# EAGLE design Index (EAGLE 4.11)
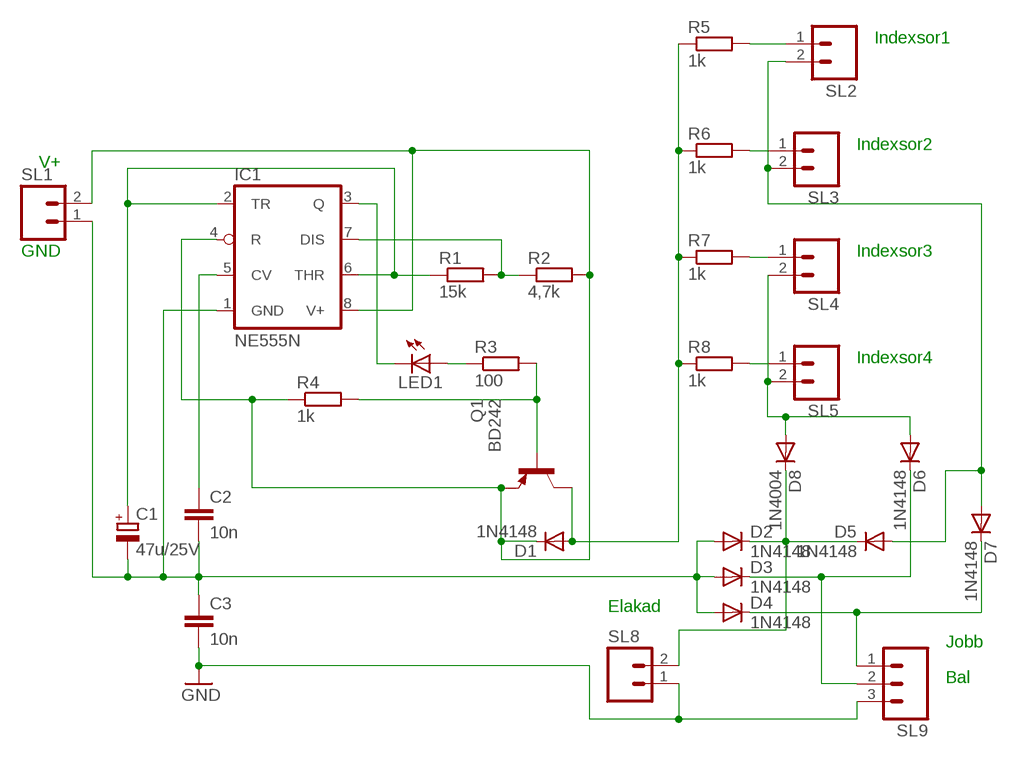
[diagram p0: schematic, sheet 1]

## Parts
C1  47u/25V  CPOL-EUE5-6  [E5-6]
C2  10n  C-EU050-025X075  [C050-025X075]
C3  10n  C-EU050-025X075  [C050-025X075]
D1  1N4148  [DO35-10]
D2  1N4148  [DO35-10]
D3  1N4148  [DO35-10]
D4  1N4148  [DO35-10]
D5  1N4148  [DO35-10]
D6  1N4148  [DO35-10]
D7  1N4148  [DO35-10]
D8  1N4004  [DO41-10]
IC1  NE555N  [DIL08]
LED1  LED5MM  [LED5MM]
Q1  BD242  [TO220]
R1  15k  R-EU_0207/10  [0207/10]
R2  4,7k  R-EU_0207/10  [0207/10]
R3  100  R-EU_0207/10  [0207/10]
R4  1k  R-EU_0207/10  [0207/10]
R5  1k  R-EU_0207/10  [0207/10]
R6  1k  R-EU_0207/10  [0207/10]
R7  1k  R-EU_0207/10  [0207/10]
R8  1k  R-EU_0207/10  [0207/10]
SL1  M02  [02P]
SL2  M02  [02P]
SL3  M02  [02P]
SL4  M02  [02P]
SL5  M02  [02P]
SL8  M02  [02P]
SL9  M03  [03P]

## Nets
GND: C3.2 SL8.1 SL9.3
N$1: C1.- C2.2 C3.1 D2.A D3.A D4.A IC1.1(GND) SL1.1
N$2: D1.A Q1.2(C) R5.1 R6.1 R7.1 R8.1
N$3: C1.+ IC1.2(TR) IC1.6(THR) R1.1
N$4: D4.C D7.C SL9.1
N$5: R5.2 SL2.1
N$6: IC1.7(DIS) R1.2 R2.1
N$7: R6.2 SL3.1
N$8: IC1.3(Q) LED1.K(C)
N$9: LED1.A R3.1
N$10: D1.C IC1.4(R) IC1.8(V+) Q1.3(E) R2.2 R4.1 SL1.2
N$11: Q1.1(B) R3.2 R4.2
N$12: R7.2 SL4.1
N$13: R8.2 SL5.1
N$14: D5.A D7.A SL2.2 SL3.2
N$15: D6.A D8.A SL4.2 SL5.2
N$16: C2.1 IC1.5(CV)
N$19: D2.C D5.C D8.C SL8.2
N$21: D3.C D6.C SL9.2

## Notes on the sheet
- Indexsor1
- Indexsor2
- V+
- GND | Indexsor3
- Indexsor4
- Elakad
- Jobb
- Bal

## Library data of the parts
C1 = rcl:CPOL-EU: POLARIZED CAPACITOR, European symbol
C2 C3 = rcl:C-EU: CAPACITOR, European symbol
D1-D7 = diode:1N4148: DIODE
D8 = diode:1N4004: DIODE
IC1 = linear:*555: TIMER
LED1 = led:LED: LED
Q1 = transistor-pnp:BD242: PNP Transistor
R1-R8 = rcl:R-EU_: RESISTOR, European symbol
SL1-SL5 SL8 = con-amp-quick:M02: AMP QUICK CONNECTOR
SL9 = con-amp-quick:M03: AMP QUICK CONNECTOR

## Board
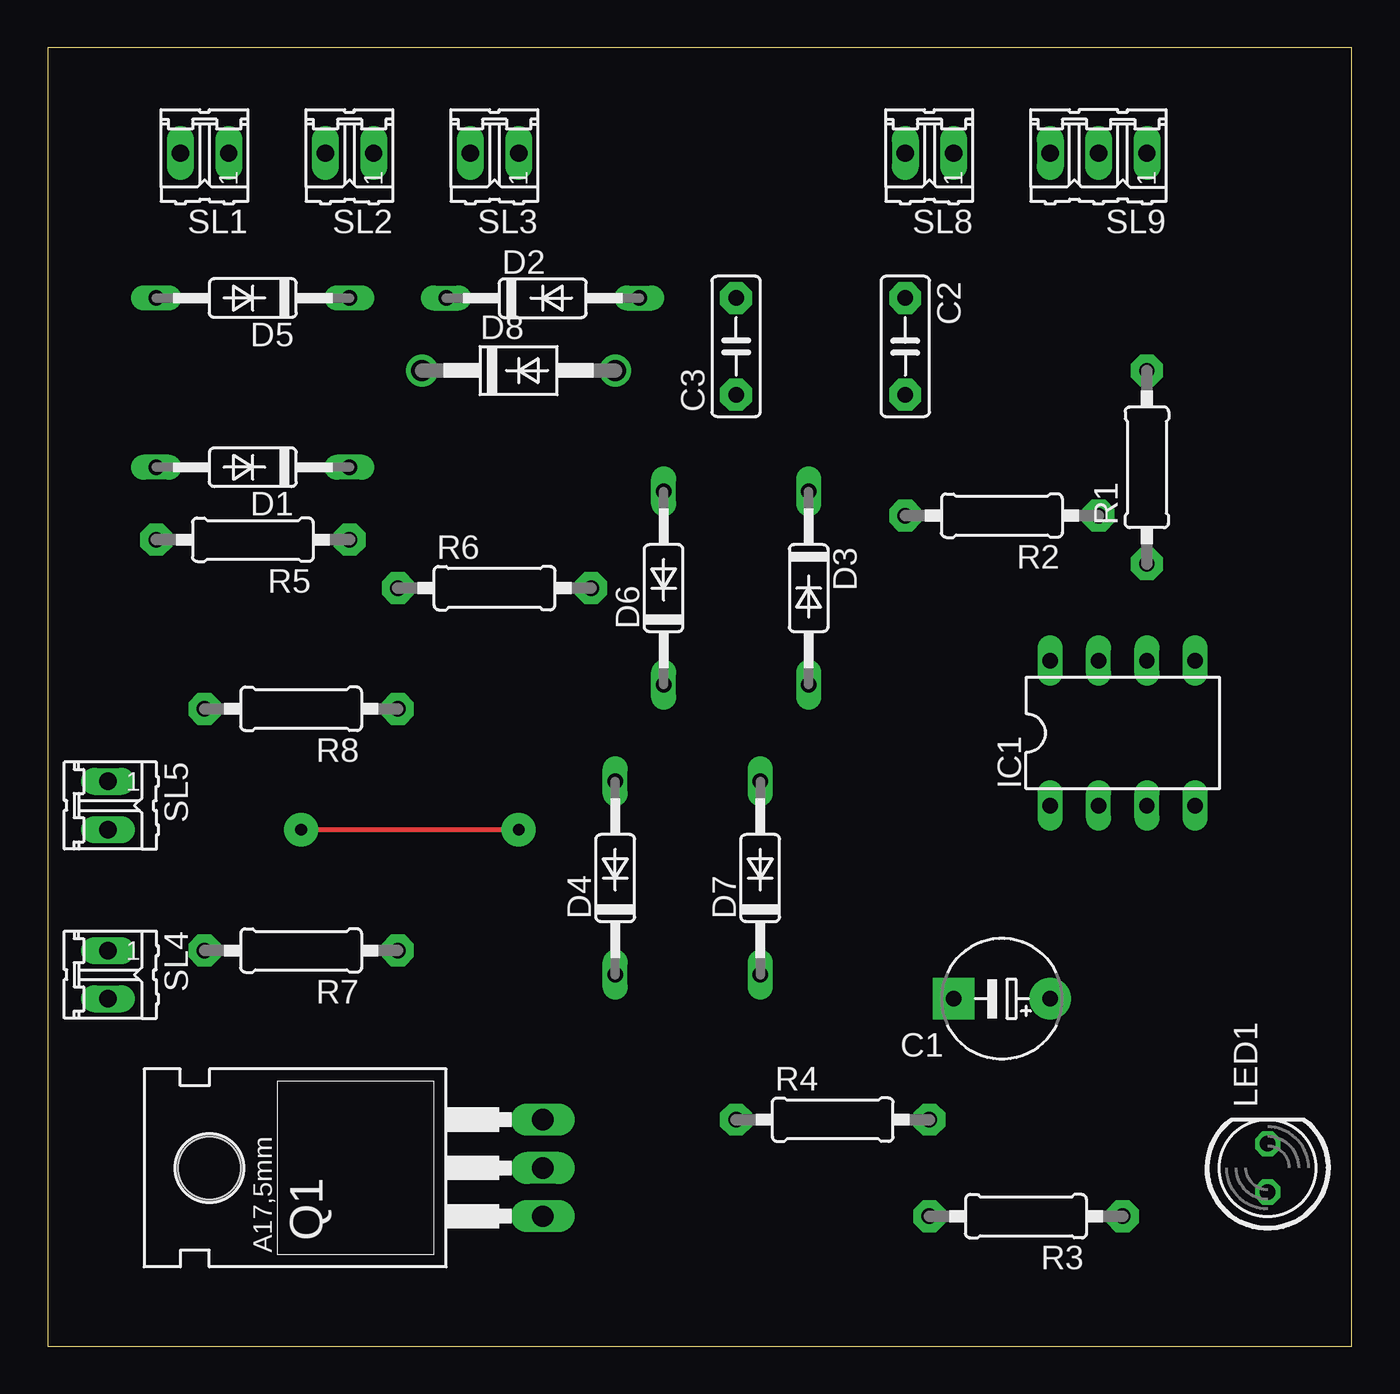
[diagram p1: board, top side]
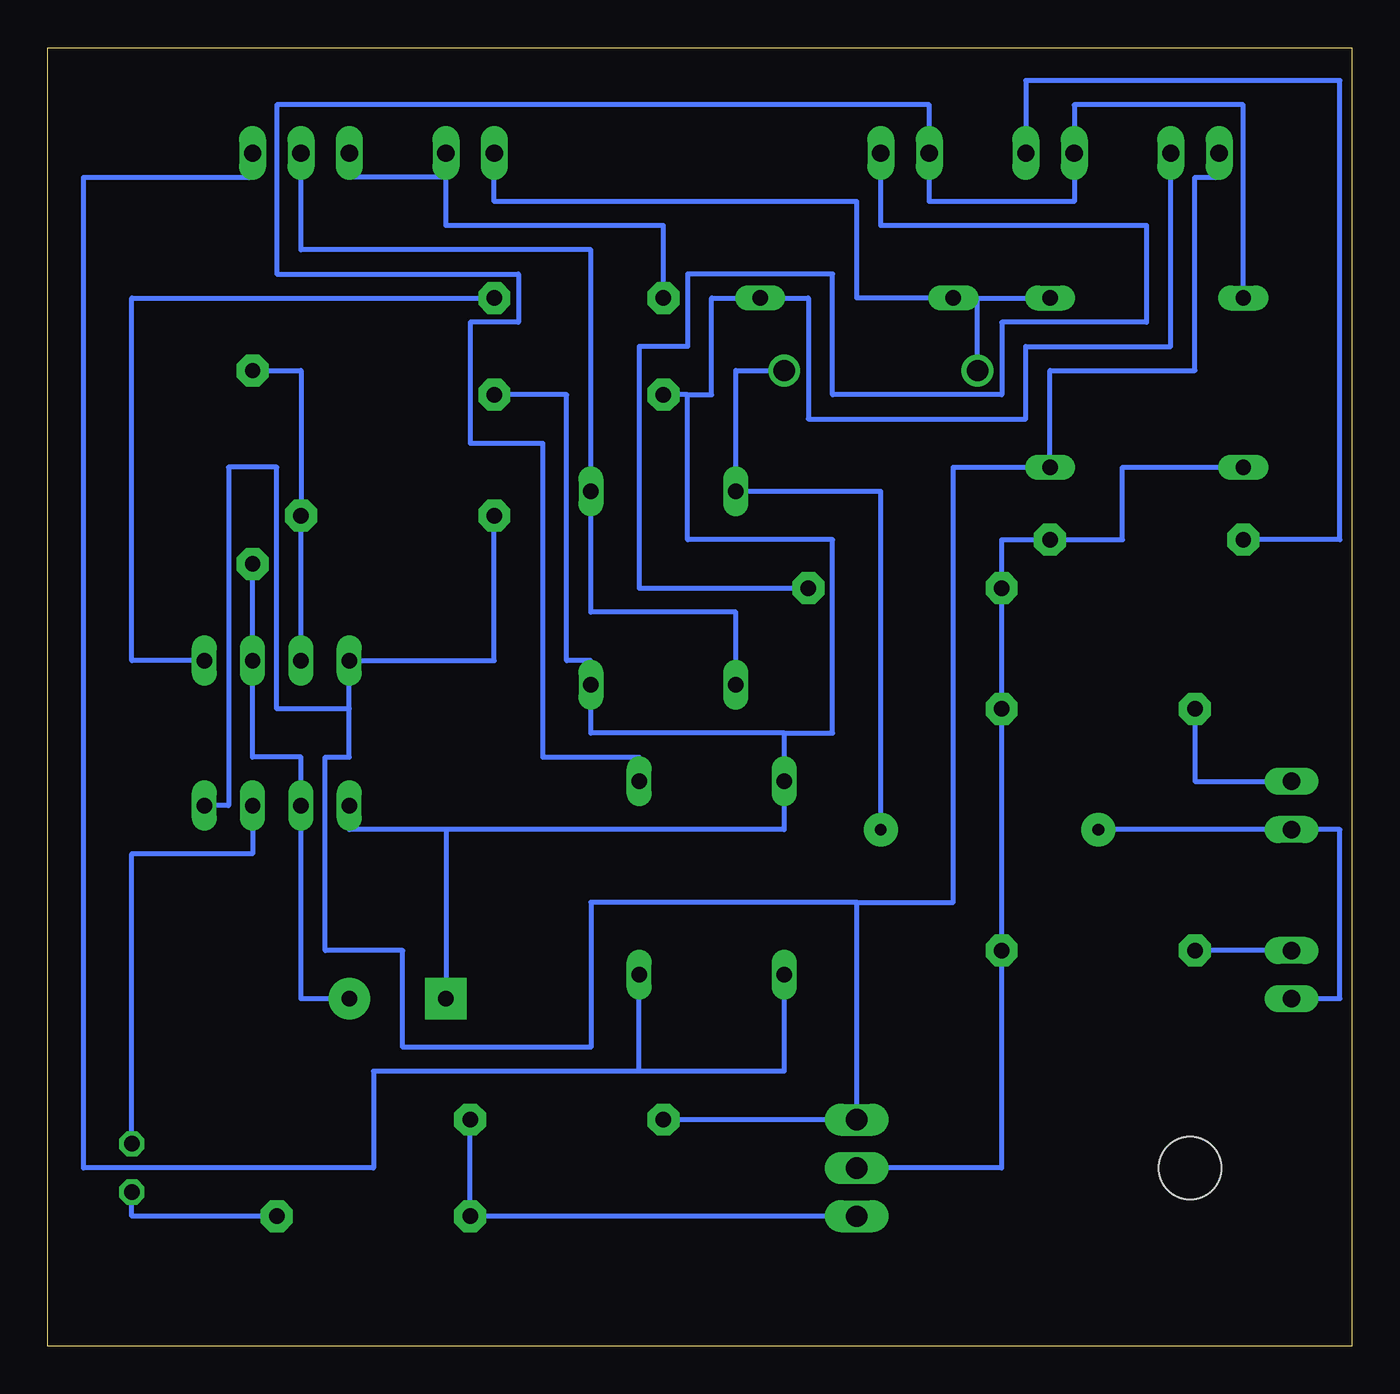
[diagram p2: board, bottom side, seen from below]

Size 68.56 x 68.25 mm. Coordinates in mm from the lower left corner, seen from the top.
Outline: 0,0 68.56,0 68.56,68.25 0,68.25 0,0
Copper layers (1*16): Top 0.035mm / dielectric 1.5mm / Bottom 0.035mm
Design rules "default": minimum track width 10mil, minimum drill 24mil, track to track 8mil, track to pad 8mil, pad to pad 8mil, via to via 8mil, smd to smd 8mil, copper to edge 40mil, drill to drill 8mil, minimum pad ring 10mil, minimum via ring 8mil, stop-mask expansion 4mil, vias tented up to drill 0mil, thermal gap 10mil

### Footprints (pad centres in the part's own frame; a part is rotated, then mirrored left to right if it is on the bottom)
E5-6 = drill 0.813 pad 2.184 round: + -2.54,0 | drill 0.813 pad 2.184 square: - 2.54,0
C050-025X075 = drill 0.813 pad 1.676 octagon: 1 -2.54,0; 2 2.54,0
DO35-10 = drill 0.813 long: A 5.08,0; C -5.08,0
DO41-10 = drill 1.118 round: A 5.08,0; C -5.08,0
DIL08 = drill 0.813 long: 1 -3.81,-3.81; 2 -1.27,-3.81; 3 1.27,-3.81; 4 3.81,-3.81; 5 3.81,3.81; 6 1.27,3.81; 7 -1.27,3.81; 8 -3.81,3.81
LED5MM = drill 0.813 octagon: A -1.27,0; K 1.27,0
TO220 = drill 1.118 long: 1 -2.54,-6.35; 2 0,-6.35; 3 2.54,-6.35 | hole 3.302: 0,11.176
0207/10 = drill 0.813 pad 1.676 octagon: 1 -5.08,0; 2 5.08,0
02P = drill 0.914 long: 1 -1.27,0; 2 1.27,0
03P = drill 0.914 long: 1 -2.54,0; 2 0,0; 3 2.54,0

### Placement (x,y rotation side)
C1  50.16,18.25 180 top
C2  45.08,52.54 270 top
C3  36.19,52.54 90 top
D1  10.79,46.19 180 top
D2  26.03,55.08 0 top
D3  40,39.84 270 top
D4  29.84,24.6 90 top
D5  10.79,55.08 180 top
D6  32.38,39.84 90 top
D7  37.46,24.6 90 top
D8  24.76,51.27 0 top
IC1  56.51,32.22 0 top
LED1  64.13,9.36 90 top
Q1  19.68,9.36 90 top
R1  57.78,46.19 90 top
R2  50.16,43.65 180 top
R3  51.43,6.82 180 top
R4  41.27,11.9 0 top
R5  10.79,42.38 180 top
R6  23.49,39.84 0 top
R7  13.33,20.79 180 top
R8  13.33,33.49 180 top
SL1  8.25,62.7 180 top
SL2  15.87,62.7 180 top
SL3  23.49,62.7 180 top
SL4  3.17,19.52 270 top
SL5  3.17,28.41 270 top
SL8  46.35,62.7 180 top
SL9  55.24,62.7 180 top

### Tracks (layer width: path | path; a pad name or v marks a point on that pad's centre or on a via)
GND
  Bottom 0.254: 47.62,61.43 52.7,61.43 SL9.3 | C3.2 36.19,58.89 47.62,58.89 47.62,61.43 | 47.62,61.43 SL8.1
N$1
  Bottom 0.254: 34.92,50 33.65,50 33.65,55.08 D2.A 28.57,55.08 28.57,48.73 17.14,48.73 17.14,52.54 9.52,52.54 SL1.1 | 34.92,50 C3.1 | 47.62,27.14 52.7,27.14 IC1.1 | 29.84,32.22 40,32.22 D3.A 40,36.03 41.27,36.03 41.27,50 C2.2 | 29.84,32.22 D4.A 29.84,27.14 47.62,27.14 | 47.62,27.14 C1.- | 29.84,32.22 27.3,32.22 27.3,42.38 34.92,42.38 34.92,50
N$2
  Bottom 0.254: Q1.2 18.41,9.36 R7.1 R8.1 R6.1 18.41,42.38 R5.1 12.06,42.38 12.06,46.19 D1.A
N$3
  Bottom 0.254: R1.1 IC1.6 57.78,30.95 55.24,30.95 IC1.2 55.24,18.25 C1.+
N$4
  Bottom 0.254: 37.46,14.44 29.84,14.44 D4.C | 37.46,14.44 51.43,14.44 51.43,9.36 66.67,9.36 66.67,61.43 57.78,61.43 SL9.1 | 37.46,14.44 D7.C
N$5
  Bottom 0.254: R5.2 0.63,42.38 0.63,66.51 17.14,66.51 SL2.1
N$6
  Bottom 0.254: IC1.7 R2.1 55.24,51.27 R1.2
N$7
  Bottom 0.254: SL3.1 24.76,58.89 10.79,58.89 10.79,53.81 18.41,53.81 18.41,50 27.3,50 27.3,56.35 34.92,56.35 34.92,52.54 37.46,52.54 37.46,39.84 R6.2
N$8
  Bottom 0.254: LED1.K 64.13,25.87 57.78,25.87 IC1.3
N$9
  Bottom 0.254: LED1.A 64.13,6.82 R3.1
N$10
  Bottom 0.254: SL1.2 6.98,61.43 8.25,61.43 8.25,51.27 15.87,51.27 D1.C 20.95,46.19 20.95,23.33 26.03,23.33 | R2.2 45.08,36.03 IC1.8 52.7,33.49 | 26.03,23.33 40,23.33 40,15.71 49.9,15.71 49.9,20.79 53.97,20.79 53.97,30.95 52.7,30.95 52.7,33.49 | 26.03,23.33 Q1.3 R4.1 | IC1.4 59.05,28.41 59.05,46.19 56.51,46.19 56.51,33.49 52.7,33.49
N$11
  Bottom 0.254: Q1.1 R3.2 R4.2
N$12
  Bottom 0.254: SL4.1 R7.2
N$13
  Bottom 0.254: R8.2 8.25,29.68 SL5.1
N$14
  Bottom 0.254: D5.A 5.71,65.24 14.6,65.24 SL2.2 14.6,60.16 22.22,60.16 SL3.2 22.22,65.24 56.51,65.24 56.51,56.35 43.81,56.35 43.81,53.81 46.35,53.81 46.35,47.46 42.54,47.46 42.54,30.95 37.46,30.95 D7.A
N$15  (via drill 0.61 pad 1.78)
  Top 0.254: v13.33,27.14 v24.76,27.14
  Bottom 0.254: D8.A 32.38,51.27 D6.A 24.76,44.92 v24.76,27.14 | SL4.2 0.63,18.25 0.63,27.14 SL5.2 v13.33,27.14
N$16
  Bottom 0.254: IC1.5 64.13,36.03 64.13,55.08 C2.1
N$19
  Bottom 0.254: 19.68,55.08 D5.C | SL8.2 45.08,60.16 26.03,60.16 26.03,55.08 D2.C 19.68,55.08 | D8.C 19.68,55.08
N$21
  Bottom 0.254: D6.C 32.38,38.57 40,38.57 D3.C 40,57.62 55.24,57.62 SL9.2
